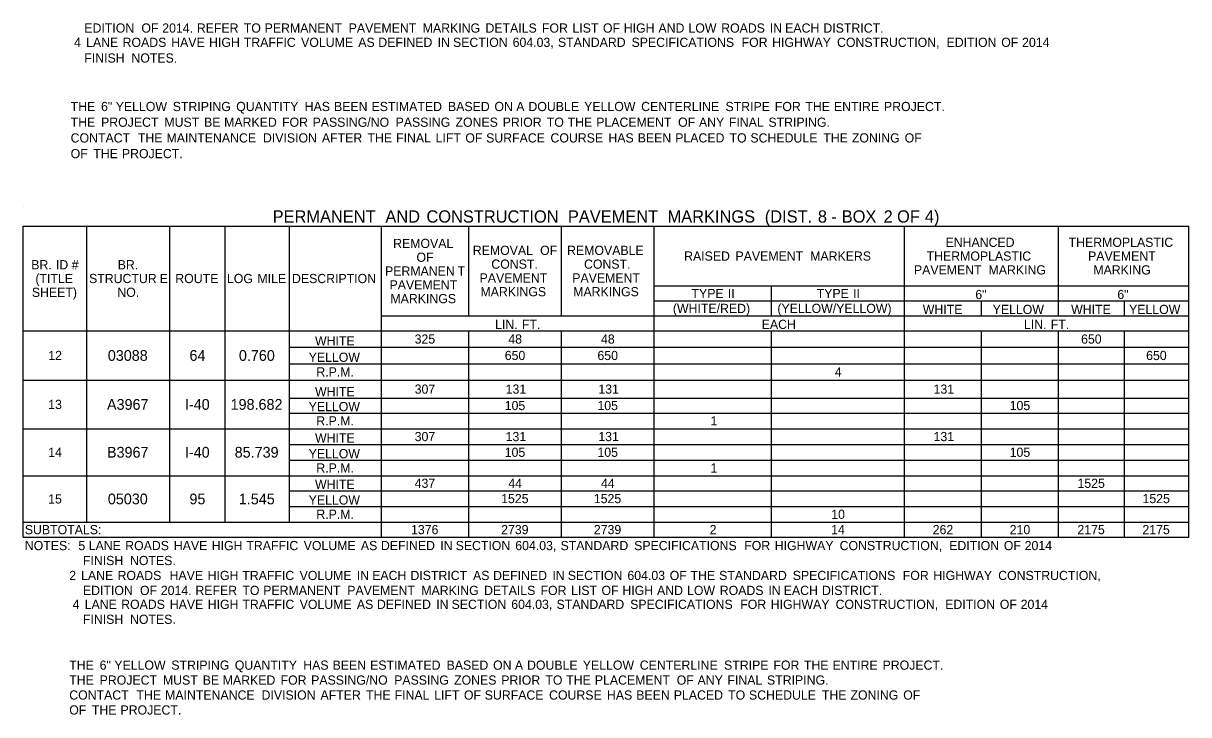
# Model space of a CAD drawing. Extents: x 540541 to 1930787, y -1948574 to 596640.
# Drawn here: x 540655 to 541415, y -1948502 to -1948051 of the extents above; entities that cross this region are included whole.
import ezdxf

# ---------------------------------------------------------------- set-up
doc = ezdxf.new("R2010")
doc.units = 0
doc.layers.add('Default', color=7, linetype='Continuous')
doc.layers.add('R_Border', color=7, linetype='Continuous')

msp = doc.modelspace()

# ---------------------------------------------------------------- linework, layer by layer
at = {"layer": 'Default'}
for p, q in [((540654.54, -1948183.35), (541414.55, -1948183.35)), ((540654.54, -1948386.15), (540654.54, -1948183.35)), ((540695.97, -1948376.4), (540695.97, -1948183.35)), ((540750.09, -1948376.4), (540750.09, -1948183.35)), ((540786.16, -1948376.4), (540786.16, -1948183.35)), ((540828.09, -1948376.4), (540828.09, -1948183.35)), ((540888.05, -1948386.15), (540888.05, -1948183.35)), ((540945.09, -1948241.85), (540945.09, -1948183.35)), ((541005.54, -1948241.85), (541005.54, -1948183.35)), ((541065.99, -1948386.15), (541065.99, -1948183.35)), ((541229.3, -1948386.15), (541229.3, -1948183.35)), ((541329.72, -1948241.85), (541329.72, -1948183.35)), ((541414.55, -1948222.35), (541414.55, -1948183.35)), ((541065.99, -1948222.35), (541414.55, -1948222.35)), ((541142.52, -1948241.85), (541142.52, -1948222.35)), ((541329.72, -1948241.85), (541329.72, -1948222.35)), ((541414.55, -1948241.85), (541414.55, -1948222.35)), ((541065.99, -1948232.1), (541414.55, -1948232.1)), ((541279.51, -1948241.85), (541279.51, -1948232.1)), ((541372.62, -1948241.85), (541372.62, -1948232.1)), ((540888.05, -1948241.85), (541414.55, -1948241.85)), ((541414.55, -1948251.6), (541414.55, -1948241.85)), ((540654.54, -1948251.6), (541414.55, -1948251.6)), ((540828.09, -1948251.6), (541329.72, -1948251.6)), ((540828.09, -1948376.4), (540828.09, -1948251.6)), ((540888.05, -1948273.05), (540888.05, -1948251.6)), ((540945.09, -1948386.15), (540945.09, -1948251.6)), ((540945.09, -1948386.15), (540945.09, -1948251.6)), ((541005.54, -1948386.15), (541005.54, -1948251.6)), ((541005.54, -1948386.15), (541005.54, -1948251.6)), ((541065.99, -1948386.15), (541065.99, -1948251.6)), ((541142.52, -1948346.18), (541142.52, -1948251.6)), ((541142.52, -1948386.15), (541142.52, -1948251.6)), ((541229.3, -1948386.15), (541229.3, -1948251.6)), ((541279.51, -1948386.15), (541279.51, -1948251.6)), ((541279.51, -1948386.15), (541279.51, -1948251.6)), ((541329.72, -1948386.15), (541329.72, -1948251.6)), ((541329.72, -1948386.15), (541329.72, -1948251.6)), ((541372.62, -1948251.6), (541414.55, -1948251.6)), ((541372.62, -1948386.15), (541372.62, -1948251.6)), ((541372.62, -1948386.15), (541372.62, -1948251.6)), ((541414.55, -1948386.15), (541414.55, -1948251.6)), ((540828.09, -1948262.33), (541414.55, -1948262.33)), ((540828.09, -1948273.05), (541414.55, -1948273.05)), ((541372.62, -1948273.05), (541414.55, -1948273.05)), ((540654.54, -1948283.78), (541414.55, -1948283.78)), ((540828.09, -1948283.78), (541329.72, -1948283.78)), ((540888.05, -1948305.23), (540888.05, -1948283.78)), ((541372.62, -1948283.78), (541414.55, -1948283.78)), ((540828.09, -1948295.48), (541414.55, -1948295.48)), ((540828.09, -1948305.23), (541414.55, -1948305.23)), ((540654.54, -1948315.46), (541414.55, -1948315.46)), ((540828.09, -1948315.46), (541414.55, -1948315.46)), ((540888.05, -1948335.94), (540888.05, -1948315.46)), ((540828.09, -1948325.7), (541414.55, -1948325.7)), ((540828.09, -1948335.94), (541414.55, -1948335.94)), ((540654.54, -1948346.18), (541372.62, -1948346.18)), ((540828.09, -1948346.18), (541065.99, -1948346.18)), ((540888.05, -1948366.16), (540888.05, -1948346.18)), ((541142.52, -1948346.18), (541329.72, -1948346.18)), ((541329.72, -1948346.18), (541372.62, -1948346.18)), ((541372.62, -1948346.18), (541414.55, -1948346.18)), ((541372.62, -1948346.18), (541414.55, -1948346.18)), ((540828.09, -1948355.93), (541414.55, -1948355.93)), ((540828.09, -1948366.16), (541414.55, -1948366.16)), ((541372.62, -1948366.16), (541414.55, -1948366.16)), ((540654.54, -1948376.4), (541414.55, -1948376.4)), ((540888.05, -1948386.15), (540888.05, -1948376.4)), ((541142.52, -1948386.15), (541142.52, -1948376.4)), ((540654.54, -1948386.15), (541414.55, -1948386.15))]:
    msp.add_line(p, q, dxfattribs=at)
at = {"layer": 'R_Border'}
msp.add_line((540654.54, -1948170.68), (540654.54, -1948170.68), dxfattribs=at)

# ---------------------------------------------------------------- texts
at = {"layer": 'Default'}
for s, height, p in [('                 EDITION', 6, (540656.43, -1948057.08)), (' OF', 6, (540729.32, -1948057.08)), (' 2014.', 6, (540742.9, -1948057.08)), (' REFER', 6, (540765.47, -1948057.08)), (' TO', 6, (540796.1, -1948057.08)), (' PERMANENT', 6, (540809.69, -1948057.08)), (' PAVEMENT', 6, (540864.49, -1948057.08)), (' MARKING', 6, (540912.78, -1948057.08)), (' DETAILS', 6, (540953.71, -1948057.08)), (' FOR', 6, (540990.54, -1948057.08)), (' LIST', 6, (541010.45, -1948057.08)), (' OF', 6, (541030.31, -1948057.08)), (' HIGH', 6, (541043.9, -1948057.08)), (' AND', 6, (541066.51, -1948057.08)), (' LOW', 6, (541086.09, -1948057.08)), (' ROADS', 6, (541107.42, -1948057.08)), (' IN', 6, (541139.12, -1948057.08)), (' EACH', 6, (541149.15, -1948057.08)), (' DISTRICT.', 6, (541174.09, -1948057.08)), ('              4', 6, (540656.43, -1948066.4)), (' LANE', 6, (540693.27, -1948066.4)), (' ROADS', 6, (540717.05, -1948066.4)), (' HAVE', 6, (540748.76, -1948066.4)), (' HIGH', 6, (540773.47, -1948066.4)), (' TRAFFIC', 6, (540796.08, -1948066.4)), (' VOLUME', 6, (540833.47, -1948066.4)), (' AS', 6, (540870.75, -1948066.4)), (' DEFINED', 6, (540883.83, -1948066.4)), (' IN', 6, (540922.51, -1948066.4)), (' SECTION', 6, (540932.53, -1948066.4)), (' 604.03,', 6, (540971.44, -1948066.4)), (' STANDARD', 6, (541000.98, -1948066.4)), (' SPECIFICATIONS', 6, (541048.98, -1948066.4)), (' FOR', 6, (541120.75, -1948066.4)), (' HIGHWAY', 6, (541140.66, -1948066.4)), (' CONSTRUCTION,', 6, (541182.98, -1948066.4)), (' EDITION', 6, (541254.43, -1948066.4)), (' OF', 6, (541290.07, -1948066.4)), (' 2014', 6, (541303.66, -1948066.4)), ('                 FINISH', 6, (540656.43, -1948076.64)), (' NOTES.', 6, (540722.8, -1948076.64)), ('             THE', 6, (540656.43, -1948108.27)), (' 6"', 6, (540703.01, -1948108.27)), (' YELLOW', 6, (540712.58, -1948108.27)), (' STRIPING', 6, (540749.75, -1948108.27)), (' QUANTITY', 6, (540791.15, -1948108.27)), (' HAS', 6, (540835.8, -1948108.27)), (' BEEN', 6, (540854.93, -1948108.27)), (' ESTIMATED', 6, (540879.41, -1948108.27)), (' BASED', 6, (540929.27, -1948108.27)), (' ON', 6, (540959.57, -1948108.27)), (' A', 6, (540973.79, -1948108.27)), (' DOUBLE', 6, (540981.73, -1948108.27)), (' YELLOW', 6, (541018.08, -1948108.27)), (' CENTERLINE', 6, (541055.25, -1948108.27)), (' STRIPE', 6, (541110.24, -1948108.27)), (' FOR', 6, (541142.41, -1948108.27)), (' THE', 6, (541162.32, -1948108.27)), (' ENTIRE', 6, (541180.97, -1948108.27)), (' PROJECT.', 6, (541213.59, -1948108.27)), ('             THE', 6, (540656.43, -1948118.51)), (' PROJECT', 6, (540703.01, -1948118.51)), (' MUST', 6, (540744.3, -1948118.51)), (' BE', 6, (540770.21, -1948118.51)), (' MARKED', 6, (540783.28, -1948118.51)), (' FOR', 6, (540821.03, -1948118.51)), (' PASSING/NO', 6, (540840.94, -1948118.51)), (' PASSING', 6, (540895.07, -1948118.51)), (' ZONES', 6, (540934.15, -1948118.51)), (' PRIOR', 6, (540964.93, -1948118.51)), (' TO', 6, (540993.69, -1948118.51)), (' THE', 6, (541007.29, -1948118.51)), (' PLACEMENT', 6, (541025.94, -1948118.51)), (' OF', 6, (541079.34, -1948118.51)), (' ANY', 6, (541092.93, -1948118.51)), (' FINAL', 6, (541112.43, -1948118.51)), (' STRIPING.', 6, (541138.22, -1948118.51)), ('             CONTACT', 6, (540656.43, -1948128.75)), (' THE', 6, (540727.04, -1948128.75)), (' MAINTENANCE', 6, (540745.69, -1948128.75)), (' DIVISION', 6, (540808.6, -1948128.75)), (' AFTER', 6, (540847.04, -1948128.75)), (' THE', 6, (540876.74, -1948128.75)), (' FINAL', 6, (540895.39, -1948128.75)), (' LIFT', 6, (540921.17, -1948128.75)), (' OF', 6, (540940.56, -1948128.75)), (' SURFACE', 6, (540954.15, -1948128.75)), (' COURSE', 6, (540996.1, -1948128.75)), (' HAS', 6, (541033.85, -1948128.75)), (' BEEN', 6, (541052.98, -1948128.75)), (' PLACED', 6, (541077.45, -1948128.75)), (' TO', 6, (541112.88, -1948128.75)), (' SCHEDULE', 6, (541126.48, -1948128.75)), (' THE', 6, (541174.02, -1948128.75)), (' ZONING', 6, (541192.66, -1948128.75)), (' OF', 6, (541227.07, -1948128.75)), ('             OF', 6, (540656.43, -1948138.98)), (' THE', 6, (540697.95, -1948138.98)), (' PROJECT.', 6, (540716.6, -1948138.98)), ('PERMANENT', 8, (540817.13, -1948181.01)), (' AND', 8, (540887.7, -1948181.01)), (' CONSTRUCTION', 8, (540914.47, -1948181.01)), (' PAVEMENT', 8, (541006.73, -1948181.01)), (' MARKINGS', 8, (541071.72, -1948181.01)), (' (DIST.', 8, (541135.13, -1948181.01)), (' 8', 8, (541169.75, -1948181.01)), (' -', 8, (541178.57, -1948181.01)), (' BOX', 8, (541185.31, -1948181.01)), (' 2', 8, (541212.63, -1948181.01)), (' OF', 8, (541221.39, -1948181.01)), (' 4)', 8, (541239.5, -1948181.01)), ('REMOVAL', 6, (540895.73, -1948197.6)), ('ENHANCED', 6, (541255.96, -1948196.85)), ('THERMOPLASTIC', 6, (541336.25, -1948196.85)), ('OF', 6, (540910.94, -1948206.6)), ('REMOVAL', 6, (540947.68, -1948202.1)), (' OF', 6, (540989.35, -1948202.1)), ('REMOVABLE', 6, (541009.18, -1948202.1)), ('RAISED', 6, (541085.49, -1948205.85)), (' PAVEMENT', 6, (541116.75, -1948205.85)), (' MARKERS', 6, (541165.49, -1948205.85)), ('THERMOPLASTIC', 6, (541243.63, -1948205.85)), ('PAVEMENT', 6, (541348.93, -1948205.85)), ('BR.', 6, (540659.73, -1948211.48)), (' ID', 6, (540673.59, -1948211.48)), (' #', 6, (540683.89, -1948211.48)), ('BR.', 6, (540716.1, -1948211.48)), ('CONST.', 6, (540959.76, -1948211.1)), ('CONST.', 6, (541020.21, -1948211.1)), ('(TITLE', 6, (540662.42, -1948220.48)), ('STRUCTUR', 6, (540697.41, -1948220.48)), ('E', 6, (540743.48, -1948220.48)), ('ROUTE', 6, (540753.66, -1948220.48)), ('LOG', 6, (540787.33, -1948220.48)), (' MILE', 6, (540804.98, -1948220.48)), ('DESCRIPTION', 6, (540829.75, -1948220.48)), ('PERMANEN', 6, (540890.44, -1948215.6)), ('T', 6, (540937.75, -1948215.6)), ('PAVEMENT', 6, (540952.1, -1948220.1)), ('PAVEMENT', 6, (541012.55, -1948220.1)), ('PAVEMENT', 6, (541235.37, -1948214.85)), (' MARKING', 6, (541281.78, -1948214.85)), ('MARKING', 6, (541352.36, -1948214.85)), ('SHEET)', 6, (540660.1, -1948229.48)), ('NO.', 6, (540715.86, -1948229.48)), ('PAVEMENT', 6, (540893.36, -1948224.6)), ('MARKINGS', 6, (540952.69, -1948229.1)), ('MARKINGS', 6, (541013.14, -1948229.1)), ('MARKINGS', 6, (540893.95, -1948233.6)), ('TYPE', 6, (541090.29, -1948230.23)), (' II', 6, (541111.78, -1948230.23)), ('TYPE', 6, (541171.95, -1948230.23)), (' II', 6, (541193.43, -1948230.23)), ('6"', 6, (541275.4, -1948230.9)), ('6"', 6, (541368.03, -1948230.9)), ('(WHITE/RED)', 6, (541078.16, -1948239.98)), ('(YELLOW/YELLOW)', 6, (541146.31, -1948239.98)), ('WHITE', 6, (541241.11, -1948240.65)), ('YELLOW', 6, (541286.69, -1948240.65)), ('WHITE', 6, (541337.88, -1948240.65)), ('YELLOW', 6, (541375.66, -1948240.65)), ('LIN.', 6, (540962.23, -1948250.4)), (' FT.', 6, (540977.48, -1948250.4)), ('EACH', 6, (541136.08, -1948250.4)), ('LIN.', 6, (541307.13, -1948250.4)), (' FT.', 6, (541322.39, -1948250.4)), ('325', 6, (540909.74, -1948259.96)), ('48', 6, (540970.84, -1948259.96)), ('48', 6, (541031.29, -1948259.96)), ('650', 6, (541344.38, -1948259.96)), ('WHITE', 6, (540844.79, -1948261.13)), ('12', 6, (540670.82, -1948270.69)), ('03088', 7, (540709.65, -1948271.19)), ('64', 7, (540762.92, -1948271.19)), ('0.760', 7, (540795.13, -1948271.19)), ('YELLOW', 6, (540840.64, -1948271.85)), ('650', 6, (540968.52, -1948270.69)), ('650', 6, (541028.97, -1948270.69)), ('650', 6, (541386.8, -1948270.69)), ('R.P.M.', 6, (540845.63, -1948281.41)), ('4', 6, (541183.78, -1948281.41)), ('WHITE', 6, (540844.79, -1948294.28)), ('307', 6, (540909.77, -1948292.63)), ('131', 6, (540969.09, -1948292.63)), ('131', 6, (541029.54, -1948292.63)), ('131', 6, (541248.18, -1948292.63)), ('13', 6, (540670.78, -1948302.62)), ('A3967', 7, (540709.11, -1948303.12)), ('I-40', 7, (540759.94, -1948303.12)), ('198.682', 7, (540789.71, -1948303.12)), ('YELLOW', 6, (540840.64, -1948304.03)), ('105', 6, (540968.49, -1948303.35)), ('105', 6, (541028.94, -1948303.35)), ('105', 6, (541297.79, -1948303.35)), ('R.P.M.', 6, (540845.63, -1948313.34)), ('1', 6, (541102.69, -1948313.34)), ('WHITE', 6, (540844.79, -1948324.5)), ('307', 6, (540909.77, -1948323.58)), ('131', 6, (540969.09, -1948323.58)), ('131', 6, (541029.54, -1948323.58)), ('131', 6, (541248.18, -1948323.58)), ('14', 6, (540670.8, -1948333.82)), ('B3967', 7, (540709.11, -1948334.32)), ('I-40', 7, (540759.94, -1948334.32)), ('85.739', 7, (540792.39, -1948334.32)), ('YELLOW', 6, (540840.64, -1948334.74)), ('105', 6, (540968.49, -1948333.82)), ('105', 6, (541028.94, -1948333.82)), ('105', 6, (541297.79, -1948333.82)), ('R.P.M.', 6, (540845.63, -1948344.06)), ('1', 6, (541102.69, -1948344.06)), ('WHITE', 6, (540844.79, -1948354.73)), ('437', 6, (540909.77, -1948354.05)), ('44', 6, (540970.85, -1948354.05)), ('44', 6, (541031.3, -1948354.05)), ('1525', 6, (541342.02, -1948354.05)), ('15', 6, (540670.76, -1948364.29)), ('05030', 7, (540709.67, -1948364.79)), ('95', 7, (540762.88, -1948364.79)), ('1.545', 7, (540795.09, -1948364.79)), ('YELLOW', 6, (540840.64, -1948364.96)), ('1525', 6, (540966.16, -1948364.04)), ('1525', 6, (541026.61, -1948364.04)), ('1525', 6, (541384.43, -1948364.04)), ('R.P.M.', 6, (540845.63, -1948374.28)), ('10', 6, (541181.45, -1948374.28)), ('SUBTOTALS:', 6, (540655.51, -1948384.28)), ('1376', 6, (540907.39, -1948384.28)), ('2739', 6, (540966.18, -1948384.28)), ('2739', 6, (541026.63, -1948384.28)), ('2', 6, (541102.13, -1948384.28)), ('14', 6, (541181.35, -1948384.28)), ('262', 6, (541247.62, -1948384.28)), ('210', 6, (541297.83, -1948384.28)), ('2175', 6, (541341.98, -1948384.28)), ('2175', 6, (541384.39, -1948384.28)), ('NOTES:', 6, (540655.51, -1948394.7)), ('  5', 6, (540685.99, -1948394.7)), (' LANE', 6, (540694.97, -1948394.7)), (' ROADS', 6, (540718.75, -1948394.7)), (' HAVE', 6, (540750.46, -1948394.7)), (' HIGH', 6, (540775.17, -1948394.7)), (' TRAFFIC', 6, (540797.78, -1948394.7)), (' VOLUME', 6, (540835.17, -1948394.7)), (' AS', 6, (540872.46, -1948394.7)), (' DEFINED', 6, (540885.53, -1948394.7)), (' IN', 6, (540924.21, -1948394.7)), (' SECTION', 6, (540934.24, -1948394.7)), (' 604.03,', 6, (540973.14, -1948394.7)), (' STANDARD', 6, (541002.68, -1948394.7)), (' SPECIFICATIONS', 6, (541050.68, -1948394.7)), (' FOR', 6, (541122.45, -1948394.7)), (' HIGHWAY', 6, (541142.36, -1948394.7)), (' CONSTRUCTION,', 6, (541184.68, -1948394.7)), (' EDITION', 6, (541256.13, -1948394.7)), (' OF', 6, (541291.77, -1948394.7)), (' 2014', 6, (541305.36, -1948394.7)), ('                 FINISH', 6, (540655.51, -1948404.45)), (' NOTES.', 6, (540721.89, -1948404.45)), ('             2', 6, (540655.51, -1948414.2)), (' LANE', 6, (540689.99, -1948414.2)), (' ROADS', 6, (540713.77, -1948414.2)), ('  HAVE', 6, (540745.47, -1948414.2)), (' HIGH', 6, (540772.51, -1948414.2)), (' TRAFFIC', 6, (540795.12, -1948414.2)), (' VOLUME', 6, (540832.51, -1948414.2)), (' IN', 6, (540869.8, -1948414.2)), (' EACH', 6, (540879.82, -1948414.2)), (' DISTRICT', 6, (540904.77, -1948414.2)), (' AS', 6, (540945.59, -1948414.2)), (' DEFINED', 6, (540958.66, -1948414.2)), (' IN', 6, (540997.34, -1948414.2)), (' SECTION', 6, (541007.37, -1948414.2)), (' 604.03', 6, (541046.27, -1948414.2)), (' OF', 6, (541073.85, -1948414.2)), (' THE', 6, (541087.44, -1948414.2)), (' STANDARD', 6, (541106.09, -1948414.2)), (' SPECIFICATIONS', 6, (541154.09, -1948414.2)), (' FOR', 6, (541225.85, -1948414.2)), (' HIGHWAY', 6, (541245.76, -1948414.2)), (' CONSTRUCTION,', 6, (541288.08, -1948414.2)), ('                 EDITION', 6, (540655.51, -1948423.95)), (' OF', 6, (540728.4, -1948423.95)), (' 2014.', 6, (540741.98, -1948423.95)), (' REFER', 6, (540764.55, -1948423.95)), (' TO', 6, (540795.18, -1948423.95)), (' PERMANENT', 6, (540808.78, -1948423.95)), (' PAVEMENT', 6, (540863.58, -1948423.95)), (' MARKING', 6, (540911.86, -1948423.95)), (' DETAILS', 6, (540952.79, -1948423.95)), (' FOR', 6, (540989.62, -1948423.95)), (' LIST', 6, (541009.53, -1948423.95)), (' OF', 6, (541029.39, -1948423.95)), (' HIGH', 6, (541042.98, -1948423.95)), (' AND', 6, (541065.59, -1948423.95)), (' LOW', 6, (541085.17, -1948423.95)), (' ROADS', 6, (541106.5, -1948423.95)), (' IN', 6, (541138.2, -1948423.95)), (' EACH', 6, (541148.23, -1948423.95)), (' DISTRICT.', 6, (541173.17, -1948423.95)), ('              4', 6, (540655.51, -1948433.03)), (' LANE', 6, (540692.35, -1948433.03)), (' ROADS', 6, (540716.13, -1948433.03)), (' HAVE', 6, (540747.84, -1948433.03)), (' HIGH', 6, (540772.55, -1948433.03)), (' TRAFFIC', 6, (540795.16, -1948433.03)), (' VOLUME', 6, (540832.55, -1948433.03)), (' AS', 6, (540869.84, -1948433.03)), (' DEFINED', 6, (540882.91, -1948433.03)), (' IN', 6, (540921.59, -1948433.03)), (' SECTION', 6, (540931.62, -1948433.03)), (' 604.03,', 6, (540970.52, -1948433.03)), (' STANDARD', 6, (541000.06, -1948433.03)), (' SPECIFICATIONS', 6, (541048.06, -1948433.03)), (' FOR', 6, (541119.83, -1948433.03)), (' HIGHWAY', 6, (541139.74, -1948433.03)), (' CONSTRUCTION,', 6, (541182.06, -1948433.03)), (' EDITION', 6, (541253.51, -1948433.03)), (' OF', 6, (541289.15, -1948433.03)), (' 2014', 6, (541302.74, -1948433.03)), ('                 FINISH', 6, (540655.51, -1948442.78)), (' NOTES.', 6, (540721.89, -1948442.78)), ('             THE', 6, (540655.51, -1948472.7)), (' 6"', 6, (540702.09, -1948472.7)), (' YELLOW', 6, (540711.66, -1948472.7)), (' STRIPING', 6, (540748.83, -1948472.7)), (' QUANTITY', 6, (540790.23, -1948472.7)), (' HAS', 6, (540834.88, -1948472.7)), (' BEEN', 6, (540854.01, -1948472.7)), (' ESTIMATED', 6, (540878.49, -1948472.7)), (' BASED', 6, (540928.35, -1948472.7)), (' ON', 6, (540958.66, -1948472.7)), (' A', 6, (540972.87, -1948472.7)), (' DOUBLE', 6, (540980.81, -1948472.7)), (' YELLOW', 6, (541017.17, -1948472.7)), (' CENTERLINE', 6, (541054.34, -1948472.7)), (' STRIPE', 6, (541109.32, -1948472.7)), (' FOR', 6, (541141.49, -1948472.7)), (' THE', 6, (541161.4, -1948472.7)), (' ENTIRE', 6, (541180.05, -1948472.7)), (' PROJECT.', 6, (541212.67, -1948472.7)), ('             THE', 6, (540655.51, -1948482.45)), (' PROJECT', 6, (540702.09, -1948482.45)), (' MUST', 6, (540743.38, -1948482.45)), (' BE', 6, (540769.3, -1948482.45)), (' MARKED', 6, (540782.36, -1948482.45)), (' FOR', 6, (540820.11, -1948482.45)), (' PASSING/NO', 6, (540840.02, -1948482.45)), (' PASSING', 6, (540894.16, -1948482.45)), (' ZONES', 6, (540933.23, -1948482.45)), (' PRIOR', 6, (540964.01, -1948482.45)), (' TO', 6, (540992.77, -1948482.45)), (' THE', 6, (541006.37, -1948482.45)), (' PLACEMENT', 6, (541025.02, -1948482.45)), (' OF', 6, (541078.42, -1948482.45)), (' ANY', 6, (541092.01, -1948482.45)), (' FINAL', 6, (541111.51, -1948482.45)), (' STRIPING.', 6, (541137.3, -1948482.45)), ('             CONTACT', 6, (540655.51, -1948492.2)), (' THE', 6, (540726.12, -1948492.2)), (' MAINTENANCE', 6, (540744.77, -1948492.2)), (' DIVISION', 6, (540807.68, -1948492.2)), (' AFTER', 6, (540846.12, -1948492.2)), (' THE', 6, (540875.82, -1948492.2)), (' FINAL', 6, (540894.47, -1948492.2)), (' LIFT', 6, (540920.26, -1948492.2)), (' OF', 6, (540939.65, -1948492.2)), (' SURFACE', 6, (540953.23, -1948492.2)), (' COURSE', 6, (540995.18, -1948492.2)), (' HAS', 6, (541032.93, -1948492.2)), (' BEEN', 6, (541052.06, -1948492.2)), (' PLACED', 6, (541076.53, -1948492.2)), (' TO', 6, (541111.96, -1948492.2)), (' SCHEDULE', 6, (541125.56, -1948492.2)), (' THE', 6, (541173.1, -1948492.2)), (' ZONING', 6, (541191.75, -1948492.2)), (' OF', 6, (541226.15, -1948492.2)), ('             OF', 6, (540655.51, -1948501.95)), (' THE', 6, (540697.03, -1948501.95)), (' PROJECT.', 6, (540715.68, -1948501.95))]:
    msp.add_text(s, height=height, dxfattribs=at).set_placement(p)

doc.saveas('drawing.dxf')
